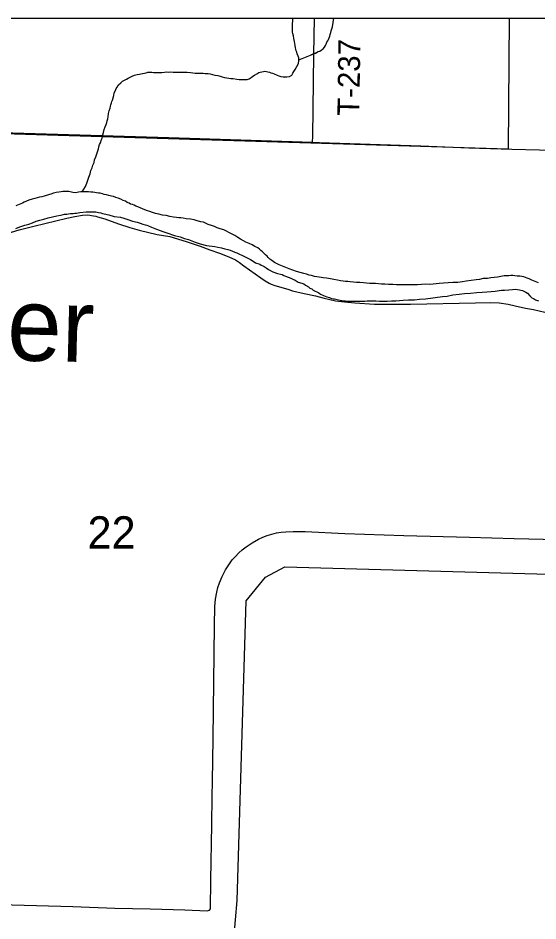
# Model space of a CAD drawing. Extents: x 0 to 68, y 0 to 52.9.
# Drawn here: x 62.63 to 64.407, y 49.856 to 52.941 of the extents above; entities that cross this region are included whole.
import ezdxf

# ---------------------------------------------------------------- set-up
doc = ezdxf.new("R2010")
doc.units = 0
for name, color, linetype in [('Default', 7, 'Continuous'), ('GM_X_Minor_Lake', 7, 'Continuous'), ('GM_X_Minor_River', 7, 'Continuous'), ('GM_X_State_Route', 7, 'Continuous'), ('GM_X_Township_Road', 7, 'Continuous'), ('GM_X_Township_Road_Text', 7, 'Continuous')]:
    doc.layers.add(name, color=color, linetype=linetype)

msp = doc.modelspace()

# ---------------------------------------------------------------- linework, layer by layer
at = {"layer": 'Default'}
msp.add_line((49.5172, 52.9414), (67.9972, 52.9414), dxfattribs=at)
for points in [[(64.3086, 52.9414), (64.3043, 52.4928), (61.6416, 52.5741), (61.6468, 52.9414)], [(62.7312, 52.3358), (62.7262, 52.3348), (62.7191, 52.3329), (62.711, 52.331), (62.7039, 52.3291), (62.6958, 52.3272), (62.6877, 52.3243), (62.6787, 52.3224), (62.6675, 52.3195), (62.6594, 52.3156), (62.6513, 52.3117), (62.6453, 52.3088), (62.623, 52.3)], [(63.6332, 52.0617), (63.6251, 52.0629), (63.6161, 52.066), (63.6061, 52.0681), (63.594, 52.0713), (63.582, 52.0755), (63.5689, 52.0797), (63.5569, 52.0848), (63.5228, 52.0984), (63.5068, 52.1056), (63.4968, 52.1128), (63.4909, 52.1179), (63.4849, 52.123), (63.4809, 52.128), (63.4759, 52.1321), (63.471, 52.1372), (63.465, 52.1423), (63.46, 52.1474), (63.455, 52.1515), (63.449, 52.1556), (63.439, 52.1607), (63.43, 52.1659), (63.42, 52.171), (63.409, 52.1752), (63.4, 52.1803), (63.39, 52.1855), (63.381, 52.1916), (63.371, 52.1978), (63.36, 52.204), (63.35, 52.2091), (63.342, 52.2132), (63.333, 52.2174), (63.321, 52.2215), (63.3109, 52.2247), (63.3009, 52.2288), (63.2909, 52.233), (63.2798, 52.2361), (63.2708, 52.2403), (63.2638, 52.2434), (63.2548, 52.2455), (63.2427, 52.2487), (63.2317, 52.2518), (63.2196, 52.254), (63.2046, 52.2552), (63.1945, 52.2574), (63.1865, 52.2585), (63.1794, 52.2586), (63.1714, 52.2597), (63.1613, 52.2608), (63.1493, 52.263), (63.1362, 52.2662), (63.1241, 52.2683), (63.1111, 52.2715), (63.1, 52.2737), (63.09, 52.2768), (63.081, 52.2799), (63.073, 52.2821), (63.0629, 52.2862), (63.0399, 52.2966), (63.0329, 52.2987), (63.0269, 52.3018), (63.0209, 52.3038), (63.0148, 52.3059), (63.0098, 52.309), (63.0028, 52.3111), (62.9968, 52.3152), (62.9898, 52.3183), (62.9808, 52.3224), (62.9718, 52.3256), (62.9638, 52.3287), (62.9568, 52.3318), (62.9497, 52.3329), (62.9407, 52.335), (62.9326, 52.3371), (62.9246, 52.3383), (62.9186, 52.3403), (62.9106, 52.3425), (62.9045, 52.3435), (62.8985, 52.3446), (62.8925, 52.3457), (62.8854, 52.3468), (62.8784, 52.3469), (62.8713, 52.347), (62.8663, 52.3471), (62.8613, 52.3471), (62.8542, 52.3472), (62.8452, 52.3473), (62.8371, 52.3464), (62.828, 52.3445), (62.8169, 52.3447), (62.8039, 52.3489), (62.7968, 52.349), (62.7898, 52.3491), (62.7827, 52.3482), (62.7777, 52.3472), (62.7696, 52.3463), (62.7605, 52.3454), (62.7514, 52.3425), (62.7423, 52.3396), (62.7373, 52.3387), (62.7312, 52.3358)], [(62.623, 52.2217), (62.6362, 52.2275), (62.6534, 52.2333), (62.6675, 52.2372), (62.6797, 52.242), (62.6918, 52.2469), (62.7049, 52.2507), (62.7181, 52.2546), (62.7332, 52.2584), (62.7484, 52.2622), (62.7625, 52.266), (62.7757, 52.2679), (62.7807, 52.2688), (62.7888, 52.2707), (62.7969, 52.2716), (62.8029, 52.2725), (62.809, 52.2735), (62.818, 52.2734), (62.8241, 52.2743), (62.8301, 52.2752), (62.8412, 52.2771), (62.8624, 52.2788), (62.8735, 52.2797), (62.8796, 52.2796), (62.8886, 52.2795), (62.8957, 52.2794), (62.9047, 52.2772), (62.9127, 52.2761), (62.9188, 52.274), (62.9248, 52.272), (62.9398, 52.2687), (62.9589, 52.2635), (62.98, 52.2612), (62.9921, 52.257), (63.0051, 52.2528), (63.0211, 52.2476), (63.0372, 52.2434), (63.0472, 52.2402), (63.0563, 52.2371), (63.0643, 52.235), (63.0703, 52.2339), (63.0763, 52.2308), (63.0864, 52.2266), (63.1034, 52.2204), (63.1154, 52.2152), (63.1244, 52.2121), (63.1385, 52.2069), (63.1646, 52.1985), (63.1846, 52.1932), (63.1987, 52.188), (63.2127, 52.1848), (63.2237, 52.1806), (63.2358, 52.1755), (63.2528, 52.1702), (63.2739, 52.1639), (63.302, 52.1605), (63.3131, 52.1584), (63.3252, 52.1562), (63.3372, 52.153), (63.3473, 52.1509), (63.3553, 52.1478), (63.3633, 52.1446), (63.3713, 52.1415), (63.3773, 52.1394), (63.3893, 52.1333), (63.3943, 52.1312), (63.4014, 52.1281), (63.4103, 52.1229), (63.4154, 52.1209), (63.4244, 52.1167), (63.4334, 52.1106), (63.4413, 52.1044), (63.4564, 52.1002), (63.4614, 52.0972), (63.4664, 52.0951), (63.4714, 52.092), (63.4774, 52.0879), (63.4854, 52.0818), (63.5004, 52.0745), (63.5164, 52.0683), (63.5265, 52.0662), (63.5325, 52.0651), (63.5385, 52.062), (63.5445, 52.0589), (63.5535, 52.0558), (63.5625, 52.0526), (63.5696, 52.0495), (63.5766, 52.0454)], [(64.4084, 52.0365), (64.3973, 52.0416), (64.3853, 52.0458), (64.3763, 52.05), (64.3703, 52.053), (64.3643, 52.0551), (64.3583, 52.0572), (64.3512, 52.0583), (64.3442, 52.0594), (64.3361, 52.0595), (64.3281, 52.0606), (64.3211, 52.0617), (64.314, 52.0618), (64.3069, 52.0609), (64.2989, 52.061), (64.2908, 52.0601), (64.2797, 52.0583), (64.2686, 52.0564), (64.2575, 52.0545), (64.2454, 52.0537), (64.2343, 52.0518), (64.2192, 52.051), (64.2071, 52.0482), (64.195, 52.0463), (64.1617, 52.0417), (64.1486, 52.0399), (64.1324, 52.0381), (64.1163, 52.0373), (64.1002, 52.0365), (64.084, 52.0357), (64.0689, 52.0339), (64.0487, 52.0322), (64.0356, 52.0313), (64.0226, 52.0315), (64.0084, 52.0307), (63.9953, 52.0299), (63.9822, 52.03), (63.9671, 52.0292), (63.952, 52.0294), (63.9379, 52.0296), (63.9238, 52.0298), (63.9107, 52.031), (63.8956, 52.0312), (63.8836, 52.0323), (63.8715, 52.0325), (63.8514, 52.0338), (63.8423, 52.0339), (63.8322, 52.034), (63.8212, 52.0352), (63.8101, 52.0363), (63.798, 52.0375), (63.787, 52.0376), (63.7769, 52.0388), (63.7648, 52.0399), (63.7568, 52.041), (63.7487, 52.0411), (63.7407, 52.0422), (63.7316, 52.0434), (63.7216, 52.0455), (63.7095, 52.0477), (63.6975, 52.0499), (63.6844, 52.052), (63.6723, 52.0542), (63.6593, 52.0564), (63.6432, 52.0586), (63.6332, 52.0617)], [(63.5766, 52.0454), (63.5876, 52.0392), (63.5996, 52.0351), (63.6066, 52.033), (63.6126, 52.0289), (63.6226, 52.0227), (63.6276, 52.0186), (63.6336, 52.0155), (63.6386, 52.0114), (63.6456, 52.0083), (63.6516, 52.0053), (63.6576, 52.0022), (63.6636, 51.9981), (63.6736, 51.9929), (63.6856, 51.9887), (63.6947, 51.9866), (63.7007, 51.9835), (63.7067, 51.9824), (63.7117, 51.9814), (63.7207, 51.9792), (63.7308, 51.9771), (63.7368, 51.976), (63.7429, 51.9749), (63.7489, 51.9748), (63.7569, 51.9737), (63.768, 51.9736), (63.7791, 51.9734), (63.7912, 51.9743), (63.8053, 51.9741), (63.8154, 51.974), (63.8234, 51.9749), (63.8315, 51.9748), (63.8415, 51.9746), (63.8526, 51.9745), (63.8647, 51.9743), (63.8788, 51.9741), (63.8909, 51.974), (63.906, 51.9748), (63.9211, 51.9756), (63.9332, 51.9764), (63.9463, 51.9773), (63.9645, 51.978), (63.9846, 51.9788), (64.0018, 51.9806), (64.0219, 51.9823), (64.0804, 51.9896), (64.0966, 51.9914), (64.1158, 51.9951), (64.1369, 51.9979), (64.1561, 51.9996), (64.1763, 52.0014), (64.1974, 52.0031), (64.2156, 52.0049), (64.2317, 52.0057), (64.2468, 52.0075), (64.261, 52.0083), (64.2741, 52.0101), (64.2821, 52.011), (64.2922, 52.0119), (64.3073, 52.0127), (64.3194, 52.0135), (64.3305, 52.0144), (64.3366, 52.0133), (64.3436, 52.0122), (64.3486, 52.0111), (64.3536, 52.0101), (64.3606, 52.007), (64.3657, 52.0049), (64.3706, 52.0008), (64.3786, 51.9917), (64.3856, 51.9856), (64.3916, 51.9825), (64.3986, 51.9783), (64.4086, 51.9752)]]:
    msp.add_lwpolyline(points, dxfattribs=at)
at = {"layer": 'GM_X_Minor_Lake'}
for points in [[(63.4761, 51.0312), (63.542, 51.0665), (65.2234, 51.0192)], [(64.4972, 47.7441), (63.7147, 48.1501), (63.4779, 48.3763), (63.2962, 48.6679), (63.2032, 49.2759), (63.2694, 49.5744), (63.362, 49.7278), (63.3786, 49.9255), (63.4096, 50.9497), (63.4761, 51.0312)]]:
    msp.add_lwpolyline(points, dxfattribs=at)
at = {"layer": 'GM_X_Minor_River'}
for points in [[(63.3506, 52.7365), (63.3567, 52.7354), (63.3647, 52.7343), (63.3778, 52.7321), (63.3858, 52.731), (63.3909, 52.7309), (63.408, 52.7317), (63.413, 52.7316), (63.4201, 52.7335), (63.4272, 52.7385), (63.4323, 52.7424), (63.4384, 52.7463), (63.4455, 52.7513), (63.4526, 52.7552), (63.4576, 52.7561), (63.4627, 52.7581), (63.4688, 52.759), (63.4738, 52.7599), (63.4788, 52.7589), (63.4839, 52.7578), (63.4889, 52.7567), (63.4939, 52.7547), (63.4999, 52.7526), (63.5049, 52.7505), (63.5159, 52.7463), (63.5209, 52.7443), (63.528, 52.7422), (63.536, 52.741), (63.542, 52.74), (63.5481, 52.7409), (63.5582, 52.7418), (63.5653, 52.7457), (63.5694, 52.7527), (63.5725, 52.7586), (63.5766, 52.7656), (63.5828, 52.7756), (63.5889, 52.7856), (63.5901, 52.7956), (63.5901, 52.8006), (63.5892, 52.8056), (63.5873, 52.8117), (63.5843, 52.8188), (63.5824, 52.8248), (63.5804, 52.8299), (63.5795, 52.8349), (63.5786, 52.8399), (63.5766, 52.848), (63.5757, 52.855), (63.5748, 52.8611), (63.5729, 52.8711), (63.571, 52.8802), (63.5691, 52.8883), (63.5682, 52.8933), (63.5682, 52.8993), (63.5683, 52.9074), (63.5684, 52.9124), (63.5688, 52.9414)], [(63.5901, 52.7982), (63.6468, 52.822), (63.6316, 52.8161), (63.6468, 52.822), (63.6559, 52.8269), (63.661, 52.8288), (63.6661, 52.8317), (63.6732, 52.8357), (63.6773, 52.8416), (63.6804, 52.8476), (63.6835, 52.8526), (63.6856, 52.8586), (63.6886, 52.8636), (63.6907, 52.8686), (63.6928, 52.8736), (63.6959, 52.8796), (63.697, 52.8856), (63.6991, 52.8916), (63.7001, 52.8976), (63.7022, 52.9046), (63.7043, 52.9116), (63.709, 52.9414)], [(62.8494, 52.3473), (62.8605, 52.3662), (62.8626, 52.3712), (62.8657, 52.3772), (62.8688, 52.3872), (62.872, 52.3982), (62.8762, 52.4092), (62.8793, 52.4202), (62.8835, 52.4292), (62.8856, 52.4382), (62.8897, 52.4482), (62.8919, 52.4572), (62.896, 52.4672), (62.9033, 52.4882), (62.9054, 52.4942), (62.9065, 52.5012), (62.9086, 52.5092), (62.9117, 52.5152), (62.9149, 52.5262), (62.917, 52.5312), (62.9191, 52.5362), (62.9201, 52.5422), (62.9223, 52.5502), (62.9244, 52.5602), (62.9275, 52.5692), (62.9317, 52.5772), (62.9338, 52.5842), (62.9348, 52.5902), (62.9369, 52.5972), (62.938, 52.6043), (62.9392, 52.6153), (62.9413, 52.6243), (62.9445, 52.6333), (62.9466, 52.6403), (62.9476, 52.6453), (62.9497, 52.6513), (62.9508, 52.6563), (62.9529, 52.6613), (62.955, 52.6683), (62.9571, 52.6763), (62.9582, 52.6864), (62.9634, 52.6943), (62.9654, 52.7003), (62.9685, 52.7053), (62.9737, 52.7133), (62.9808, 52.7202), (62.9869, 52.7252), (62.994, 52.7291), (63.0011, 52.733), (63.0062, 52.736), (63.0112, 52.7379), (63.0204, 52.7428), (63.0275, 52.7457), (63.0376, 52.7486), (63.0446, 52.7495), (63.0497, 52.7505), (63.0557, 52.7524), (63.0618, 52.7533), (63.0678, 52.7542), (63.0739, 52.7562), (63.08, 52.7561), (63.087, 52.756), (63.093, 52.7559), (63.0991, 52.7558), (63.1041, 52.7558), (63.1132, 52.7557), (63.1212, 52.7555), (63.1303, 52.7564), (63.1384, 52.7573), (63.1454, 52.7562), (63.1525, 52.7571), (63.1605, 52.757), (63.1666, 52.757), (63.1726, 52.7569), (63.1787, 52.7568), (63.1837, 52.7567), (63.1887, 52.7567), (63.1958, 52.7566), (63.2018, 52.7565), (63.2079, 52.7564), (63.2189, 52.7553), (63.227, 52.7542), (63.235, 52.753), (63.2451, 52.7529), (63.2542, 52.7528), (63.2622, 52.7527), (63.2692, 52.7516), (63.2793, 52.7515), (63.2864, 52.7504), (63.2944, 52.7482), (63.3024, 52.7461), (63.3125, 52.745), (63.3205, 52.7429), (63.3275, 52.7408), (63.3356, 52.7387), (63.3436, 52.7375), (63.3506, 52.7365)]]:
    msp.add_lwpolyline(points, dxfattribs=at)
at = {"layer": 'GM_X_State_Route'}
for points in [[(61.1206, 52.5962), (61.2222, 52.5917), (61.4033, 52.5848), (61.4928, 52.5817), (61.5498, 52.5797), (61.599, 52.5777), (61.6473, 52.577), (61.8495, 52.5702), (61.9971, 52.5655), (62.2021, 52.5597), (62.3129, 52.5571), (62.3662, 52.5559), (62.6122, 52.5488), (63.1453, 52.5327), (63.3912, 52.5249), (63.6367, 52.5169), (63.6604, 52.5161)], [(63.6604, 52.5161), (64.0062, 52.5048), (64.1702, 52.4983), (64.3178, 52.4937), (64.5064, 52.4885), (64.9621, 52.4758), (65.0559, 52.4732), (65.2445, 52.468), (65.4003, 52.4631), (65.611, 52.4562)]]:
    msp.add_lwpolyline(points, dxfattribs=at)
at = {"layer": 'GM_X_Township_Road'}
for points in [[(63.6367, 52.5169), (63.637, 52.5376), (63.6405, 52.8164), (63.643, 52.9414)], [(62.5426, 52.1902), (62.6344, 52.2173), (62.6837, 52.2299), (62.7967, 52.257), (62.8247, 52.2638), (62.8508, 52.2678), (62.8691, 52.2686), (62.8881, 52.2659), (62.8955, 52.2641), (62.9017, 52.2621), (62.9138, 52.2588), (62.9272, 52.2548), (62.9733, 52.2384), (63.0123, 52.2251), (63.0436, 52.2163), (63.1059, 52.2016), (63.1484, 52.1944), (63.2047, 52.178), (63.2527, 52.1616), (63.2856, 52.149), (63.3185, 52.1379), (63.3509, 52.125), (63.3731, 52.1146), (63.3874, 52.1066), (63.4015, 52.095), (63.4602, 52.0534), (63.474, 52.0438), (63.4882, 52.0356), (63.4954, 52.0322), (63.5081, 52.0277), (63.5521, 52.0144), (63.5677, 52.0097), (63.6078, 52.0001), (63.646, 51.9917), (63.6759, 51.984), (63.7146, 51.9753), (63.7455, 51.9714), (63.7812, 51.9686), (63.8479, 51.9638), (63.9117, 51.9638), (63.9716, 51.9638), (64.1938, 51.9687), (64.244, 51.9688), (64.274, 51.9678), (64.3043, 51.9635), (64.329, 51.9582), (64.3638, 51.9505), (64.3912, 51.9449), (64.4304, 51.9367)], [(62.5262, 49.9132), (62.817, 49.9046), (62.961, 49.8998), (63.0817, 49.897), (63.2006, 49.8932), (63.2765, 49.8899), (63.2838, 49.8923), (63.2874, 49.8973), (63.2894, 49.9955), (63.2924, 50.1842), (63.2937, 50.2826), (63.295, 50.3318), (63.2967, 50.4795), (63.3017, 50.865), (63.3028, 50.9306), (63.3048, 50.9551), (63.309, 50.9793), (63.3132, 50.9952), (63.3184, 51.0108), (63.3279, 51.0335), (63.3392, 51.0553), (63.3523, 51.0762), (63.3621, 51.0894), (63.3727, 51.1018), (63.3842, 51.1135), (63.3965, 51.1244), (63.4095, 51.1344), (63.4299, 51.1482), (63.4514, 51.1602), (63.4663, 51.1671), (63.4815, 51.1731), (63.4972, 51.178), (63.5131, 51.1817), (63.5293, 51.1844), (63.5456, 51.186), (63.5703, 51.1869), (63.6113, 51.1862), (63.7468, 51.1802), (63.9487, 51.1736), (64.1728, 51.1669), (64.3255, 51.1631), (64.9728, 51.1479)]]:
    msp.add_lwpolyline(points, dxfattribs=at)

# ---------------------------------------------------------------- texts
at = {"layer": 'Default'}
for s, height, rotation, p in [('River', 0.2501, 358.5964, (62.1079, 51.7841)), ('22', 0.1105, 0, (62.8676, 51.1282))]:
    msp.add_text(s, height=height, rotation=rotation, dxfattribs=at).set_placement(p)
at = {"layer": 'GM_X_Township_Road_Text'}
msp.add_text('T-237', height=0.075, rotation=89.1696, dxfattribs=at).set_placement((63.7962, 52.607))

doc.saveas('drawing.dxf')
